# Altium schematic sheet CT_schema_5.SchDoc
size 292 x 258 mm
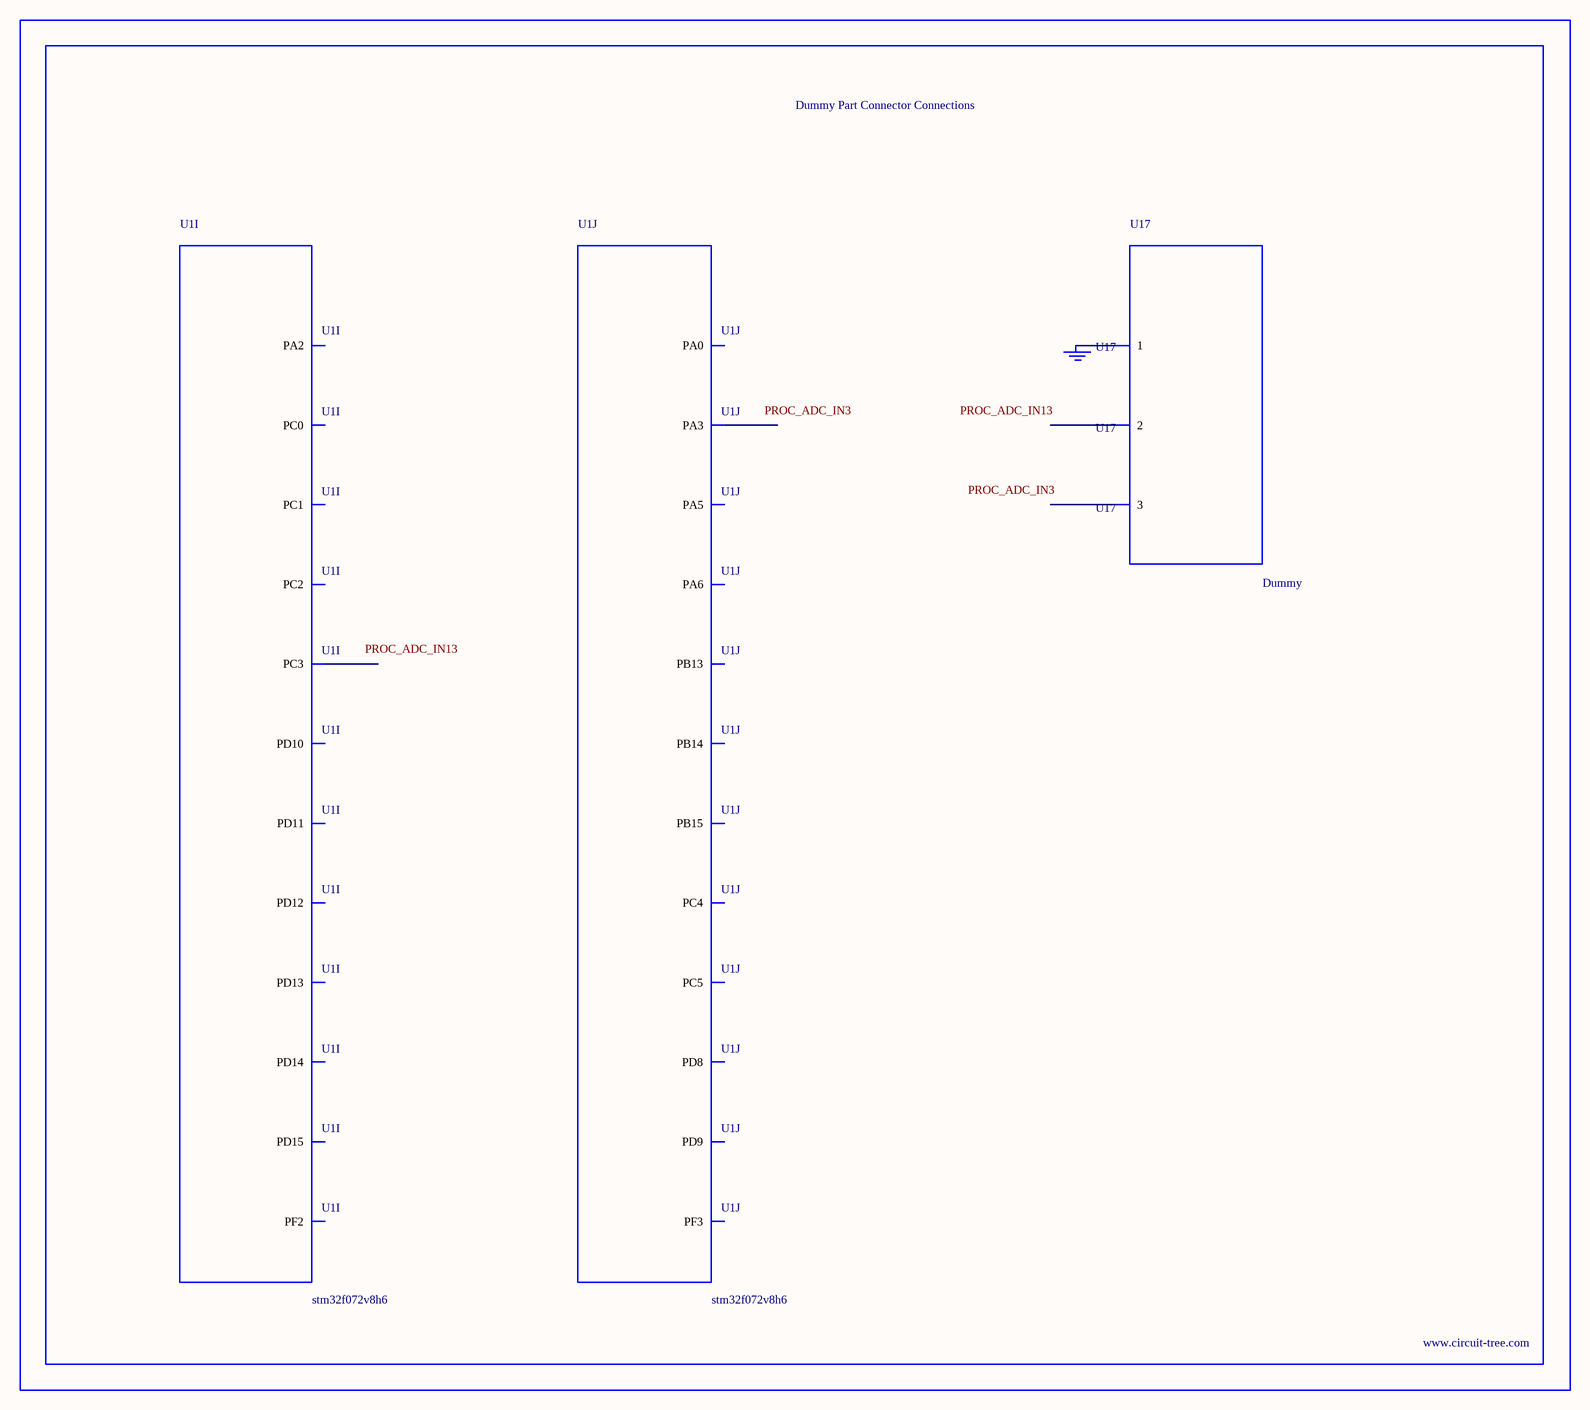
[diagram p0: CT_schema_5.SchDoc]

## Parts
BORDER4  (no value)
GND_INSTANCE_4_0  (no value)
U1  stm32f072v8h6  [UFBGA100]  (parts I,J of 10)
U17  Dummy  [DUMMY_PACKAGE_126]

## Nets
NetGND_INSTANCE_4_0_0: GND_INSTANCE_4_0.0(GND) U17.1

Not connected (* = marked no-connect by the designer): U1 H1(PC0) H10(PD15) H11(PD14) H12(PD13) J1(PF2) J2(PC1) J3(PC2) J10(PD12) J11(PD11) J12(PD10) K2(PC3) K3(PA2) K4(PA5) K5(PC4) K8(PD9) K9(PD8) K10(PB15) K11(PB14) K12(PB13) L1(PF3) L2(PA0) L3(PA3) L4(PA6) L5(PC5); U17 2 3

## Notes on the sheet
- Labels drawn without touching a wire or pin: PROC_ADC_IN3, PROC_ADC_IN13

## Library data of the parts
BORDER4 = BORDER_PAGE4
GND_INSTANCE_4_0 = GND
